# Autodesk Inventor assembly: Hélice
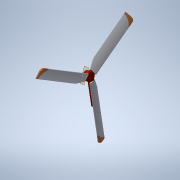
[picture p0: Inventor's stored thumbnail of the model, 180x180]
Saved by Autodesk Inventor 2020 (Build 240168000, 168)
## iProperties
Created: 2012-06
Part Number: Hélice
Document SubType Name: Assembly
Designer: Bruno
Mass: 33.8441 g
Surface Area: 261.603 cm^2
Volume: 32.2428 cm^3
Density: 1.04967 g/cm^3
Author: Bruno
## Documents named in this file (3)
- C:\Users\bruno\Documents\1-Cours-2021-22\Cours\Mécanique\Cinématique\2-Cinématique-V=W.R-Ventilo\ventilo-Inventor\Hélice.iam
- C:\Users\bruno\Documents\1-Cours-2021-22\Cours\Mécanique\Cinématique\2-Cinématique-V=W.R-Ventilo\ventilo-Inventor\Axe-helice.ipt
- C:\Users\bruno\Documents\1-Cours-2021-22\Cours\Mécanique\Cinématique\2-Cinématique-V=W.R-Ventilo\ventilo-Inventor\014 Pale2.ipt
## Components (4 placed, 2 different names)
1. Axe-helice:1 — Placage:5, Placage:6, Placage:7, Placage:8, Placage:9, Placage:10, Placage:11, Placage:12, Placage:13
2. 014 Pale2:1 — Placage:7, Placage:8, Placage:12
3. 014 Pale2:2 — Placage:9, Placage:10, Placage:13
4. 014 Pale2:3 — Placage:5, Placage:6, Placage:11
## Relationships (9: Mate 9)
- Placage:5 [Mate]: Axe-helice:1 ↔ 014 Pale2:3
- Placage:6 [Mate]: Axe-helice:1 ↔ 014 Pale2:3
- Placage:7 [Mate]: Axe-helice:1 ↔ 014 Pale2:1
- Placage:8 [Mate]: Axe-helice:1 ↔ 014 Pale2:1
- Placage:9 [Mate]: Axe-helice:1 ↔ 014 Pale2:2
- Placage:10 [Mate]: Axe-helice:1 ↔ 014 Pale2:2
- Placage:11 [Mate]: Axe-helice:1 ↔ 014 Pale2:3
- Placage:12 [Mate]: Axe-helice:1 ↔ 014 Pale2:1
- Placage:13 [Mate]: Axe-helice:1 ↔ 014 Pale2:2
